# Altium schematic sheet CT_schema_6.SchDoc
size 350 x 342 mm
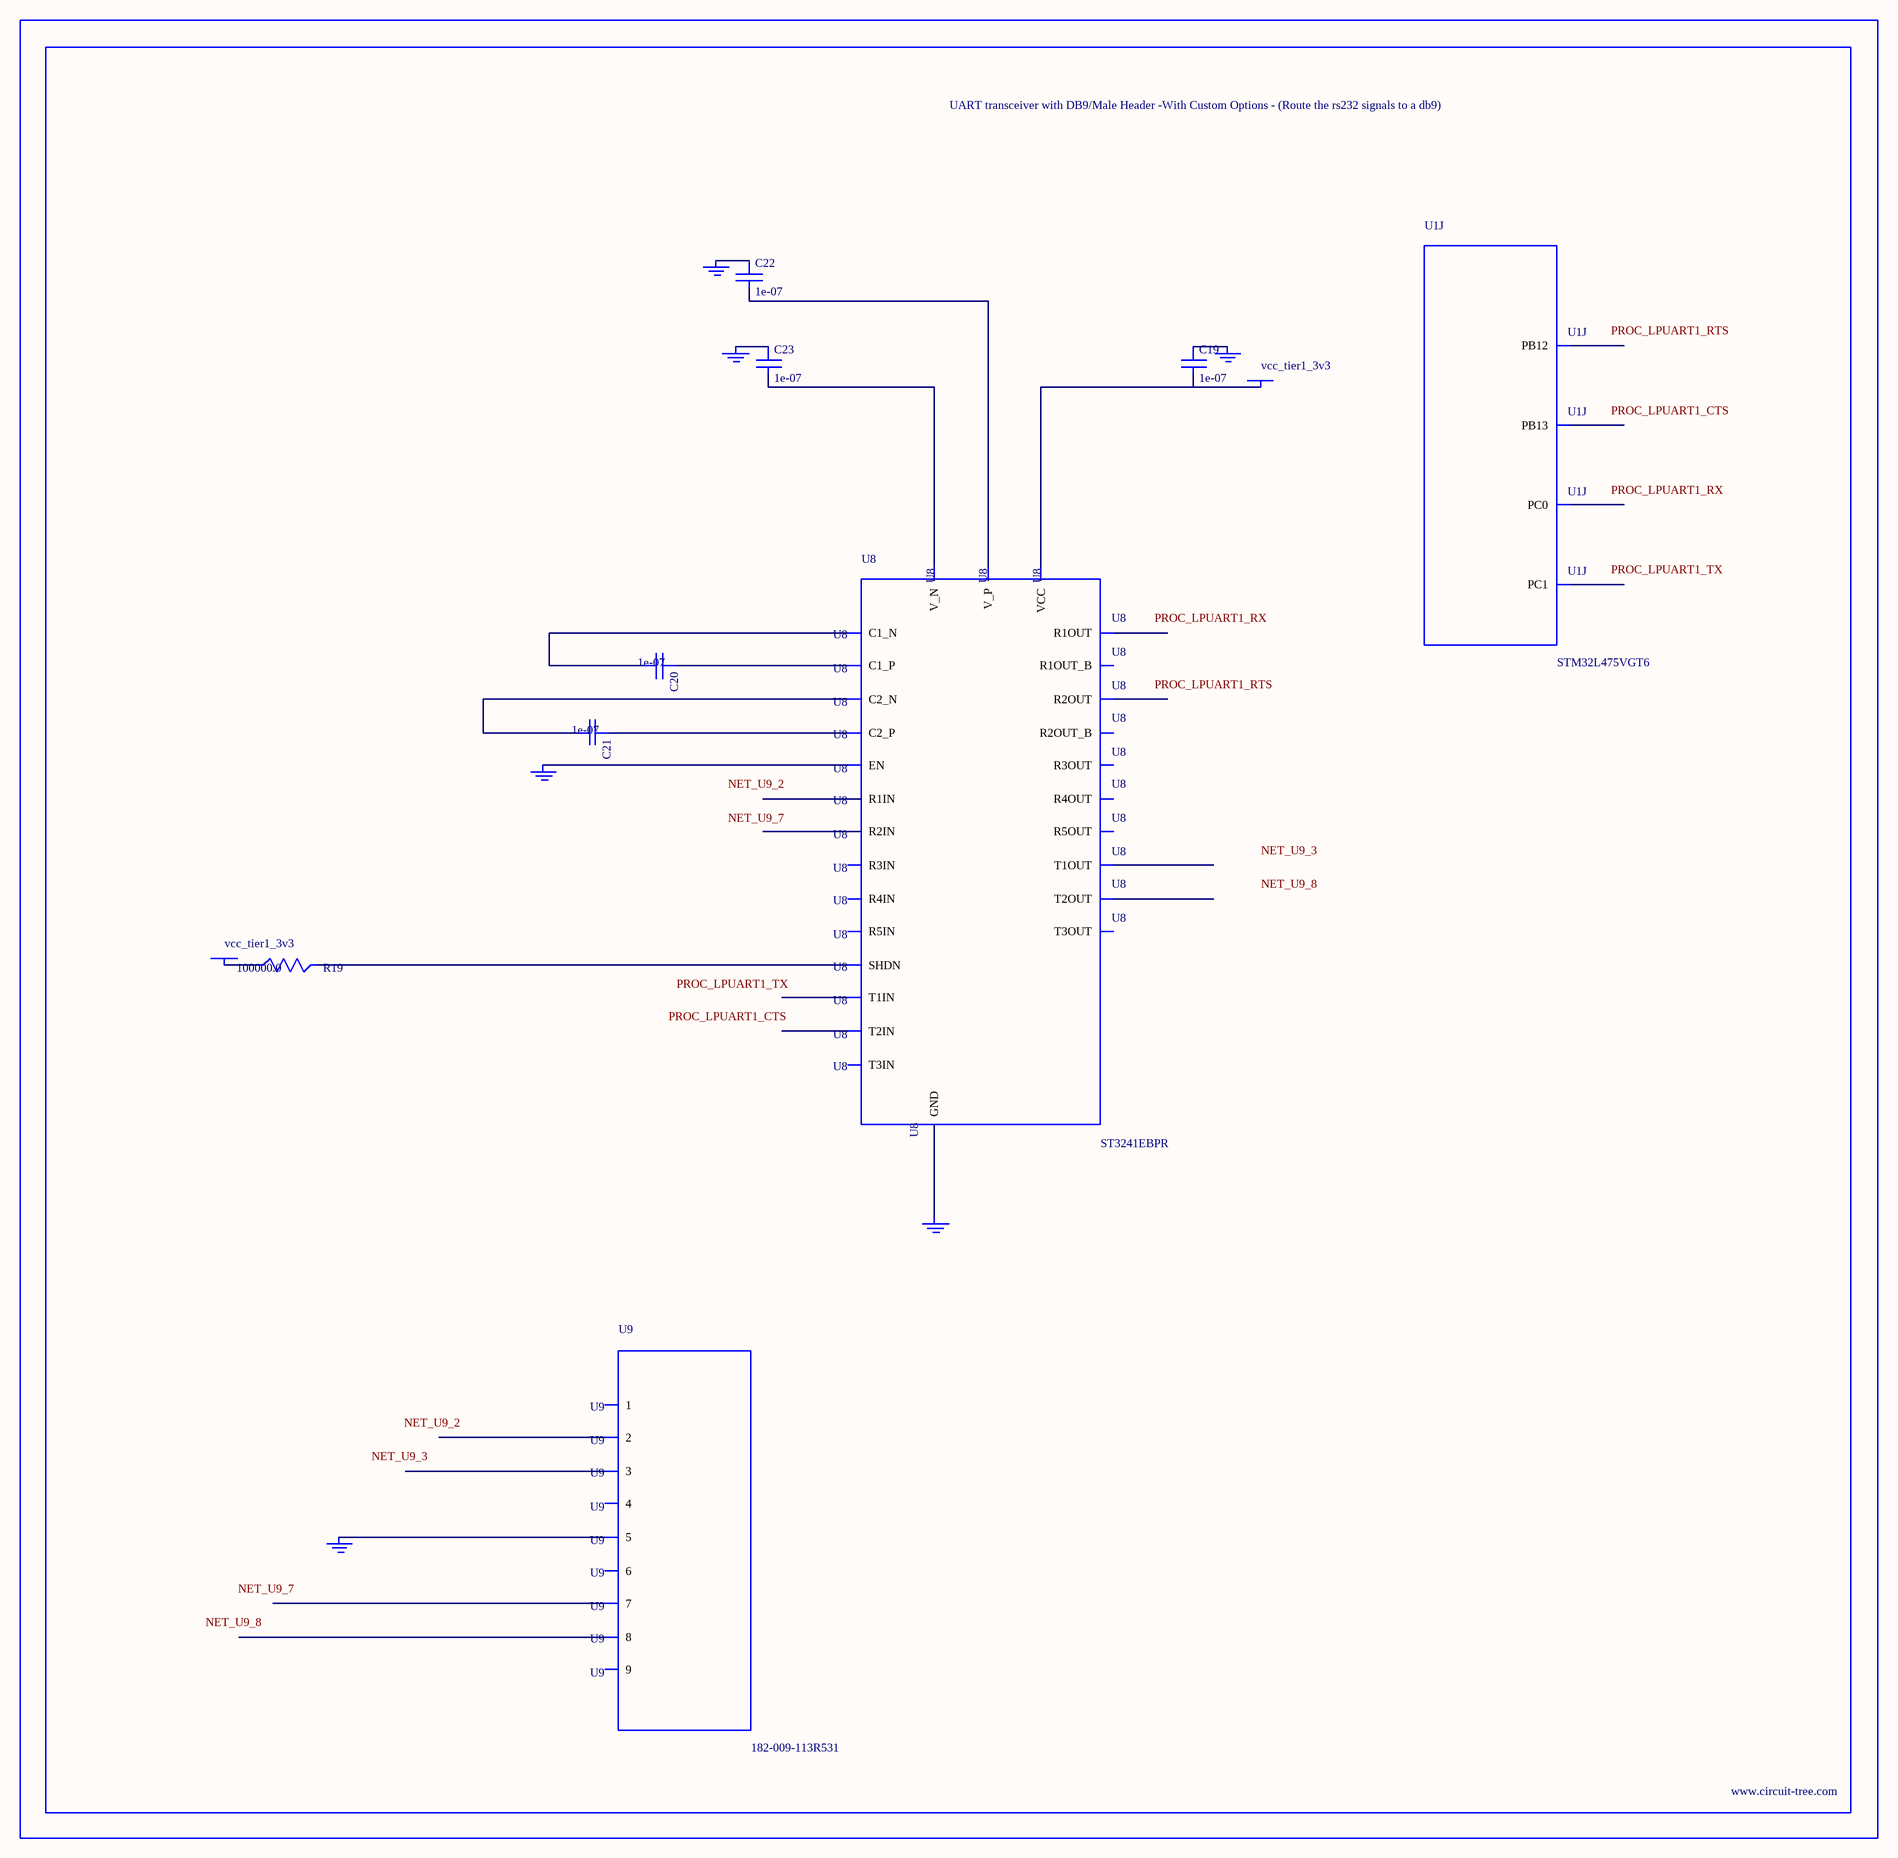
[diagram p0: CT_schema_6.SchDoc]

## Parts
BORDER5  (no value)
C19  1e-07  [C0402]
C20  1e-07  [C0402]
C21  1e-07  [C0402]
C22  1e-07  [C0402]
C23  1e-07  [C0402]
GND_INSTANCE_5_0  (no value)
GND_INSTANCE_5_1  (no value)
GND_INSTANCE_5_2  (no value)
GND_INSTANCE_5_3  (no value)
GND_INSTANCE_5_4  (no value)
GND_INSTANCE_5_5  (no value)
POWER_INSTANCE_5_0  vcc_tier1_3v3
POWER_INSTANCE_5_1  vcc_tier1_3v3
R19  100000.0  [R0603]
U1  STM32L475VGT6  [LQFP100]  (part J of 11)
U8  ST3241EBPR  [SSOP-28]
U9  182-009-113R531  [182-009-MALE]

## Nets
NetC19_1: C19.1 GND_INSTANCE_5_2.0(GND)
NetC19_2: C19.2 POWER_INSTANCE_5_1.0(PWR) U8.26(VCC)
NetC20_1: C20.1 U8.28(C1_P)
NetC20_2: C20.2 U8.24(C1_N)
NetC21_1: C21.1 U8.1(C2_P)
NetC21_2: C21.2 U8.2(C2_N)
NetC22_1: C22.1 GND_INSTANCE_5_3.0(GND)
NetC22_2: C22.2 U8.27(V_P)
NetC23_1: C23.1 GND_INSTANCE_5_0.0(GND)
NetC23_2: C23.2 U8.3(V_N)
NetGND_INSTANCE_5_1_0: GND_INSTANCE_5_1.0(GND) U8.23(EN)
NetGND_INSTANCE_5_4_0: GND_INSTANCE_5_4.0(GND) U8.25(GND)
NetGND_INSTANCE_5_5_0: GND_INSTANCE_5_5.0(GND) U9.5
NetPOWER_INSTANCE_5_0_0: POWER_INSTANCE_5_0.0(PWR) R19.1
NetR19_2: R19.2 U8.22(SHDN)

Not connected (* = marked no-connect by the designer): U1 15(PC0) 16(PC1) 51(PB12) 52(PB13); U8 4(R1IN) 5(R2IN) 6(R3IN) 7(R4IN) 8(R5IN) 9(T1OUT) 10(T2OUT) 11(T3OUT) 12(T3IN) 13(T2IN) 14(T1IN) 15(R5OUT) 16(R4OUT) 17(R3OUT) 18(R2OUT) 19(R1OUT) 20(R2OUT_B) 21(R1OUT_B); U9 1 2 3 4 6 7 8 9

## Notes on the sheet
- Labels drawn without touching a wire or pin: NET_U9_2, NET_U9_3, NET_U9_7, NET_U9_8, PROC_LPUART1_CTS, PROC_LPUART1_RTS, PROC_LPUART1_RX, PROC_LPUART1_TX

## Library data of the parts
BORDER5 = BORDER_PAGE5
C19-C23 = C0402C104K3RACTU
GND_INSTANCE_5_0-GND_INSTANCE_5_5 = GND
POWER_INSTANCE_5_0 POWER_INSTANCE_5_1 = PWR
R19 = RC0603JR-07100KL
